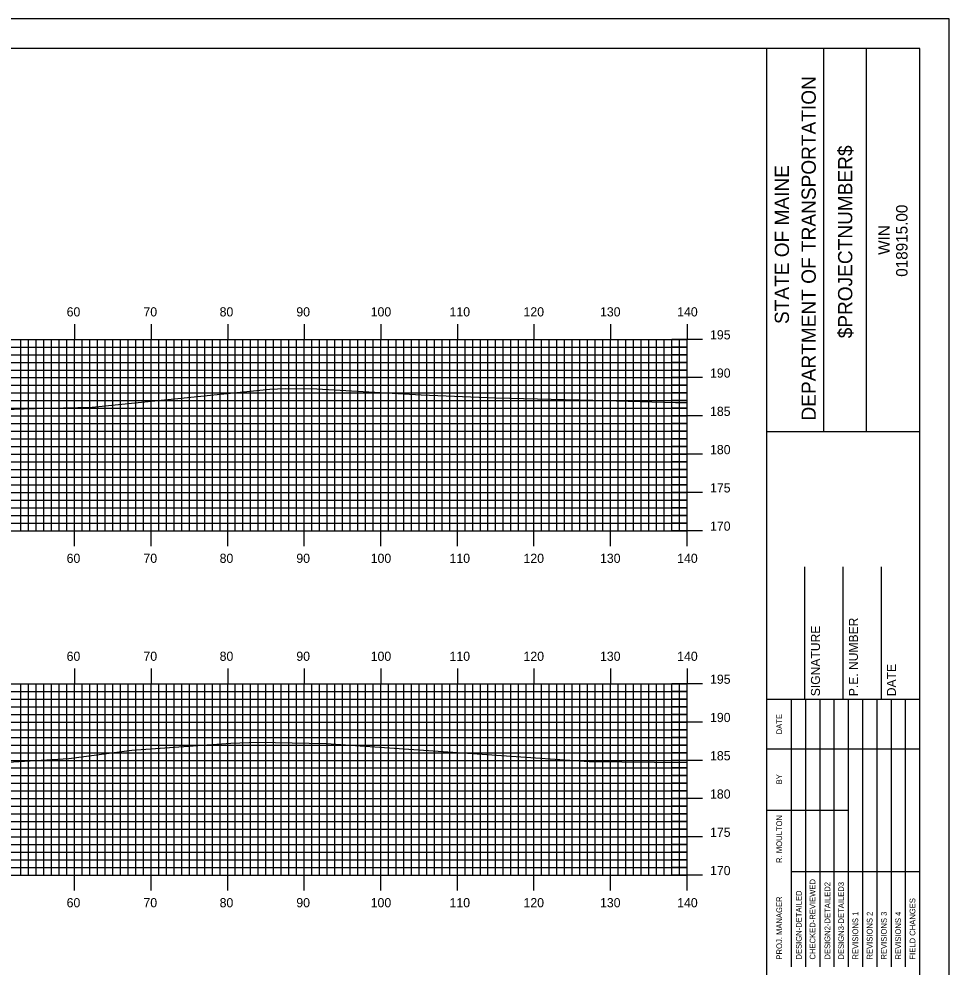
# Model space of a CAD drawing. Extents: x 1823571 to 1823914, y 442310 to 442530.
# Drawn here: x 1823789.6 to 1823911.1, y 442406.1 to 442530 of the extents above; entities that cross this region are included whole.
import ezdxf

# ---------------------------------------------------------------- set-up
doc = ezdxf.new("R2010")
doc.units = 0
for name, color, linetype in [('BORDER', 7, 'Continuous'), ('H_V ANNOTATION', 7, 'Continuous'), ('MAJOR', 7, 'Continuous'), ('MINOR', 7, 'Continuous'), ('PLOT BOUNDARY', 7, 'Continuous'), ('S_Roadway_Centerline', 7, 'Continuous')]:
    doc.layers.add(name, color=color, linetype=linetype)

msp = doc.modelspace()

# ---------------------------------------------------------------- linework, layer by layer
at = {"layer": 'BORDER'}
for p, q in [((1823887.3, 442316.11), (1823887.3, 442526.11)), ((1823894.76, 442476.1), (1823894.76, 442526.1)), ((1823900.35, 442476.1), (1823900.35, 442526.1)), ((1823887.3, 442476.09), (1823907.3, 442476.09)), ((1823892.3, 442441.11), (1823892.3, 442458.41)), ((1823897.3, 442441.11), (1823897.3, 442458.41)), ((1823902.3, 442441.11), (1823902.3, 442458.41)), ((1823887.3, 442441.11), (1823907.3, 442441.11))]:
    msp.add_line(p, q, dxfattribs=at)
msp.add_lwpolyline([(1823587.3, 442316.11), (1823907.3, 442316.11), (1823907.3, 442526.11), (1823587.3, 442526.11)], close=True, dxfattribs=at)
for points in [[(1823890.53, 442434.61), (1823890.53, 442441.11)], [(1823892.4, 442406.12), (1823892.4, 442441.11)], [(1823894.26, 442441.11), (1823894.26, 442406.12)], [(1823896.12, 442406.12), (1823896.12, 442441.11)], [(1823897.99, 442406.12), (1823897.99, 442441.11)], [(1823899.85, 442406.12), (1823899.85, 442441.11)], [(1823901.71, 442406.12), (1823901.71, 442441.11)], [(1823903.58, 442406.12), (1823903.58, 442441.11)], [(1823905.44, 442406.12), (1823905.44, 442441.11)], [(1823890.53, 442406.12), (1823890.53, 442439.7)], [(1823887.3, 442434.61), (1823907.3, 442434.61)], [(1823887.3, 442426.61), (1823890.53, 442426.61)], [(1823890.53, 442426.61), (1823897.98, 442426.61)], [(1823890.53, 442418.61), (1823907.3, 442418.61)]]:
    msp.add_lwpolyline(points, dxfattribs=at)
at = {"layer": 'MAJOR'}
for p, q in [((1823796.9, 442490.12), (1823796.9, 442488.12)), ((1823806.9, 442490.12), (1823806.9, 442488.12)), ((1823816.9, 442490.12), (1823816.9, 442488.12)), ((1823826.9, 442490.12), (1823826.9, 442488.12)), ((1823836.9, 442490.12), (1823836.9, 442488.12)), ((1823846.9, 442490.12), (1823846.9, 442488.12)), ((1823856.9, 442490.12), (1823856.9, 442488.12)), ((1823866.9, 442490.12), (1823866.9, 442488.12)), ((1823876.9, 442490.12), (1823876.9, 442488.12)), ((1823596.9, 442488.12), (1823876.9, 442488.12)), ((1823596.9, 442488.12), (1823876.9, 442488.12)), ((1823796.9, 442463.12), (1823796.9, 442488.12)), ((1823806.9, 442463.12), (1823806.9, 442488.12)), ((1823816.9, 442463.12), (1823816.9, 442488.12)), ((1823826.9, 442463.12), (1823826.9, 442488.12)), ((1823836.9, 442463.12), (1823836.9, 442488.12)), ((1823846.9, 442463.12), (1823846.9, 442488.12)), ((1823856.9, 442463.12), (1823856.9, 442488.12)), ((1823866.9, 442463.12), (1823866.9, 442488.12)), ((1823878.9, 442488.12), (1823874.9, 442488.12)), ((1823876.9, 442463.12), (1823876.9, 442488.12)), ((1823876.9, 442463.12), (1823876.9, 442488.12)), ((1823596.9, 442483.12), (1823876.9, 442483.12)), ((1823878.9, 442483.12), (1823874.9, 442483.12)), ((1823596.9, 442478.12), (1823876.9, 442478.12)), ((1823878.9, 442478.12), (1823874.9, 442478.12)), ((1823596.9, 442473.12), (1823876.9, 442473.12)), ((1823878.9, 442473.12), (1823874.9, 442473.12)), ((1823596.9, 442468.12), (1823876.9, 442468.12)), ((1823878.9, 442468.12), (1823874.9, 442468.12)), ((1823596.9, 442463.12), (1823876.9, 442463.12)), ((1823596.9, 442463.12), (1823876.9, 442463.12)), ((1823796.9, 442461.11), (1823796.9, 442463.12)), ((1823806.9, 442461.11), (1823806.9, 442463.12)), ((1823816.9, 442461.11), (1823816.9, 442463.12)), ((1823826.9, 442461.11), (1823826.9, 442463.12)), ((1823836.9, 442461.11), (1823836.9, 442463.12)), ((1823846.9, 442461.11), (1823846.9, 442463.12)), ((1823856.9, 442461.11), (1823856.9, 442463.12)), ((1823866.9, 442461.11), (1823866.9, 442463.12)), ((1823878.9, 442463.12), (1823874.9, 442463.12)), ((1823876.9, 442461.11), (1823876.9, 442463.12)), ((1823796.9, 442445.12), (1823796.9, 442443.12)), ((1823806.9, 442445.12), (1823806.9, 442443.12)), ((1823816.9, 442445.12), (1823816.9, 442443.12)), ((1823826.9, 442445.12), (1823826.9, 442443.12)), ((1823836.9, 442445.12), (1823836.9, 442443.12)), ((1823846.9, 442445.12), (1823846.9, 442443.12)), ((1823856.9, 442445.12), (1823856.9, 442443.12)), ((1823866.9, 442445.12), (1823866.9, 442443.12)), ((1823876.9, 442445.12), (1823876.9, 442443.12)), ((1823596.9, 442443.12), (1823876.9, 442443.12)), ((1823596.9, 442443.12), (1823876.9, 442443.12)), ((1823796.9, 442418.12), (1823796.9, 442443.12)), ((1823806.9, 442418.12), (1823806.9, 442443.12)), ((1823816.9, 442418.12), (1823816.9, 442443.12)), ((1823826.9, 442418.12), (1823826.9, 442443.12)), ((1823836.9, 442418.12), (1823836.9, 442443.12)), ((1823846.9, 442418.12), (1823846.9, 442443.12)), ((1823856.9, 442418.12), (1823856.9, 442443.12)), ((1823866.9, 442418.12), (1823866.9, 442443.12)), ((1823878.9, 442443.12), (1823874.9, 442443.12)), ((1823876.9, 442418.12), (1823876.9, 442443.12)), ((1823876.9, 442418.12), (1823876.9, 442443.12)), ((1823596.9, 442438.12), (1823876.9, 442438.12)), ((1823878.9, 442438.12), (1823874.9, 442438.12)), ((1823596.9, 442433.12), (1823876.9, 442433.12)), ((1823878.9, 442433.12), (1823874.9, 442433.12)), ((1823596.9, 442428.12), (1823876.9, 442428.12)), ((1823878.9, 442428.12), (1823874.9, 442428.12)), ((1823596.9, 442423.12), (1823876.9, 442423.12)), ((1823878.9, 442423.12), (1823874.9, 442423.12)), ((1823596.9, 442418.12), (1823876.9, 442418.12)), ((1823596.9, 442418.12), (1823876.9, 442418.12)), ((1823796.9, 442416.11), (1823796.9, 442418.12)), ((1823806.9, 442416.11), (1823806.9, 442418.12)), ((1823816.9, 442416.11), (1823816.9, 442418.12)), ((1823826.9, 442416.11), (1823826.9, 442418.12)), ((1823836.9, 442416.11), (1823836.9, 442418.12)), ((1823846.9, 442416.11), (1823846.9, 442418.12)), ((1823856.9, 442416.11), (1823856.9, 442418.12)), ((1823866.9, 442416.11), (1823866.9, 442418.12)), ((1823878.9, 442418.12), (1823874.9, 442418.12)), ((1823876.9, 442416.11), (1823876.9, 442418.12))]:
    msp.add_line(p, q, dxfattribs=at)
at = {"layer": 'MINOR'}
for p, q in [((1823789.9, 442463.12), (1823789.9, 442488.12)), ((1823790.9, 442463.12), (1823790.9, 442488.12)), ((1823791.9, 442463.12), (1823791.9, 442488.12)), ((1823792.9, 442463.12), (1823792.9, 442488.12)), ((1823793.9, 442463.12), (1823793.9, 442488.12)), ((1823794.9, 442463.12), (1823794.9, 442488.12)), ((1823795.9, 442463.12), (1823795.9, 442488.12)), ((1823797.9, 442463.12), (1823797.9, 442488.12)), ((1823798.9, 442463.12), (1823798.9, 442488.12)), ((1823799.9, 442463.12), (1823799.9, 442488.12)), ((1823800.9, 442463.12), (1823800.9, 442488.12)), ((1823801.9, 442463.12), (1823801.9, 442488.12)), ((1823802.9, 442463.12), (1823802.9, 442488.12)), ((1823803.9, 442463.12), (1823803.9, 442488.12)), ((1823804.9, 442463.12), (1823804.9, 442488.12)), ((1823805.9, 442463.12), (1823805.9, 442488.12)), ((1823807.9, 442463.12), (1823807.9, 442488.12)), ((1823808.9, 442463.12), (1823808.9, 442488.12)), ((1823809.9, 442463.12), (1823809.9, 442488.12)), ((1823810.9, 442463.12), (1823810.9, 442488.12)), ((1823811.9, 442463.12), (1823811.9, 442488.12)), ((1823812.9, 442463.12), (1823812.9, 442488.12)), ((1823813.9, 442463.12), (1823813.9, 442488.12)), ((1823814.9, 442463.12), (1823814.9, 442488.12)), ((1823815.9, 442463.12), (1823815.9, 442488.12)), ((1823817.9, 442463.12), (1823817.9, 442488.12)), ((1823818.9, 442463.12), (1823818.9, 442488.12)), ((1823819.9, 442463.12), (1823819.9, 442488.12)), ((1823820.9, 442463.12), (1823820.9, 442488.12)), ((1823821.9, 442463.12), (1823821.9, 442488.12)), ((1823822.9, 442463.12), (1823822.9, 442488.12)), ((1823823.9, 442463.12), (1823823.9, 442488.12)), ((1823824.9, 442463.12), (1823824.9, 442488.12)), ((1823825.9, 442463.12), (1823825.9, 442488.12)), ((1823827.9, 442463.12), (1823827.9, 442488.12)), ((1823828.9, 442463.12), (1823828.9, 442488.12)), ((1823829.9, 442463.12), (1823829.9, 442488.12)), ((1823830.9, 442463.12), (1823830.9, 442488.12)), ((1823831.9, 442463.12), (1823831.9, 442488.12)), ((1823832.9, 442463.12), (1823832.9, 442488.12)), ((1823833.9, 442463.12), (1823833.9, 442488.12)), ((1823834.9, 442463.12), (1823834.9, 442488.12)), ((1823835.9, 442463.12), (1823835.9, 442488.12)), ((1823837.9, 442463.12), (1823837.9, 442488.12)), ((1823838.9, 442463.12), (1823838.9, 442488.12)), ((1823839.9, 442463.12), (1823839.9, 442488.12)), ((1823840.9, 442463.12), (1823840.9, 442488.12)), ((1823841.9, 442463.12), (1823841.9, 442488.12)), ((1823842.9, 442463.12), (1823842.9, 442488.12)), ((1823843.9, 442463.12), (1823843.9, 442488.12)), ((1823844.9, 442463.12), (1823844.9, 442488.12)), ((1823845.9, 442463.12), (1823845.9, 442488.12)), ((1823847.9, 442463.12), (1823847.9, 442488.12)), ((1823848.9, 442463.12), (1823848.9, 442488.12)), ((1823849.9, 442463.12), (1823849.9, 442488.12)), ((1823850.9, 442463.12), (1823850.9, 442488.12)), ((1823851.9, 442463.12), (1823851.9, 442488.12)), ((1823852.9, 442463.12), (1823852.9, 442488.12)), ((1823853.9, 442463.12), (1823853.9, 442488.12)), ((1823854.9, 442463.12), (1823854.9, 442488.12)), ((1823855.9, 442463.12), (1823855.9, 442488.12)), ((1823857.9, 442463.12), (1823857.9, 442488.12)), ((1823858.9, 442463.12), (1823858.9, 442488.12)), ((1823859.9, 442463.12), (1823859.9, 442488.12)), ((1823860.9, 442463.12), (1823860.9, 442488.12)), ((1823861.9, 442463.12), (1823861.9, 442488.12)), ((1823862.9, 442463.12), (1823862.9, 442488.12)), ((1823863.9, 442463.12), (1823863.9, 442488.12)), ((1823864.9, 442463.12), (1823864.9, 442488.12)), ((1823865.9, 442463.12), (1823865.9, 442488.12)), ((1823867.9, 442463.12), (1823867.9, 442488.12)), ((1823868.9, 442463.12), (1823868.9, 442488.12)), ((1823869.9, 442463.12), (1823869.9, 442488.12)), ((1823870.9, 442463.12), (1823870.9, 442488.12)), ((1823871.9, 442463.12), (1823871.9, 442488.12)), ((1823872.9, 442463.12), (1823872.9, 442488.12)), ((1823873.9, 442463.12), (1823873.9, 442488.12)), ((1823874.9, 442463.12), (1823874.9, 442488.12)), ((1823875.9, 442463.12), (1823875.9, 442488.12)), ((1823596.9, 442487.12), (1823876.9, 442487.12)), ((1823596.9, 442486.12), (1823876.9, 442486.12)), ((1823876.9, 442487.12), (1823874.9, 442487.12)), ((1823876.9, 442486.12), (1823874.9, 442486.12)), ((1823596.9, 442485.12), (1823876.9, 442485.12)), ((1823876.9, 442485.12), (1823874.9, 442485.12)), ((1823596.9, 442484.12), (1823876.9, 442484.12)), ((1823876.9, 442484.12), (1823874.9, 442484.12)), ((1823596.9, 442482.12), (1823876.9, 442482.12)), ((1823596.9, 442481.12), (1823876.9, 442481.12)), ((1823876.9, 442482.12), (1823874.9, 442482.12)), ((1823876.9, 442481.12), (1823874.9, 442481.12)), ((1823596.9, 442480.12), (1823876.9, 442480.12)), ((1823876.9, 442480.12), (1823874.9, 442480.12)), ((1823596.9, 442479.12), (1823876.9, 442479.12)), ((1823876.9, 442479.12), (1823874.9, 442479.12)), ((1823596.9, 442477.12), (1823876.9, 442477.12)), ((1823876.9, 442477.12), (1823874.9, 442477.12)), ((1823596.9, 442476.12), (1823876.9, 442476.12)), ((1823596.9, 442475.12), (1823876.9, 442475.12)), ((1823876.9, 442476.12), (1823874.9, 442476.12)), ((1823876.9, 442475.12), (1823874.9, 442475.12)), ((1823596.9, 442474.12), (1823876.9, 442474.12)), ((1823876.9, 442474.12), (1823874.9, 442474.12)), ((1823596.9, 442472.12), (1823876.9, 442472.12)), ((1823876.9, 442472.12), (1823874.9, 442472.12)), ((1823596.9, 442471.12), (1823876.9, 442471.12)), ((1823596.9, 442470.12), (1823876.9, 442470.12)), ((1823876.9, 442471.12), (1823874.9, 442471.12)), ((1823876.9, 442470.12), (1823874.9, 442470.12)), ((1823596.9, 442469.12), (1823876.9, 442469.12)), ((1823876.9, 442469.12), (1823874.9, 442469.12)), ((1823596.9, 442467.12), (1823876.9, 442467.12)), ((1823876.9, 442467.12), (1823874.9, 442467.12)), ((1823596.9, 442466.12), (1823876.9, 442466.12)), ((1823596.9, 442465.12), (1823876.9, 442465.12)), ((1823876.9, 442466.12), (1823874.9, 442466.12)), ((1823876.9, 442465.12), (1823874.9, 442465.12)), ((1823596.9, 442464.12), (1823876.9, 442464.12)), ((1823876.9, 442464.12), (1823874.9, 442464.12)), ((1823789.9, 442418.12), (1823789.9, 442443.12)), ((1823790.9, 442418.12), (1823790.9, 442443.12)), ((1823791.9, 442418.12), (1823791.9, 442443.12)), ((1823792.9, 442418.12), (1823792.9, 442443.12)), ((1823793.9, 442418.12), (1823793.9, 442443.12)), ((1823794.9, 442418.12), (1823794.9, 442443.12)), ((1823795.9, 442418.12), (1823795.9, 442443.12)), ((1823797.9, 442418.12), (1823797.9, 442443.12)), ((1823798.9, 442418.12), (1823798.9, 442443.12)), ((1823799.9, 442418.12), (1823799.9, 442443.12)), ((1823800.9, 442418.12), (1823800.9, 442443.12)), ((1823801.9, 442418.12), (1823801.9, 442443.12)), ((1823802.9, 442418.12), (1823802.9, 442443.12)), ((1823803.9, 442418.12), (1823803.9, 442443.12)), ((1823804.9, 442418.12), (1823804.9, 442443.12)), ((1823805.9, 442418.12), (1823805.9, 442443.12)), ((1823807.9, 442418.12), (1823807.9, 442443.12)), ((1823808.9, 442418.12), (1823808.9, 442443.12)), ((1823809.9, 442418.12), (1823809.9, 442443.12)), ((1823810.9, 442418.12), (1823810.9, 442443.12)), ((1823811.9, 442418.12), (1823811.9, 442443.12)), ((1823812.9, 442418.12), (1823812.9, 442443.12)), ((1823813.9, 442418.12), (1823813.9, 442443.12)), ((1823814.9, 442418.12), (1823814.9, 442443.12)), ((1823815.9, 442418.12), (1823815.9, 442443.12)), ((1823817.9, 442418.12), (1823817.9, 442443.12)), ((1823818.9, 442418.12), (1823818.9, 442443.12)), ((1823819.9, 442418.12), (1823819.9, 442443.12)), ((1823820.9, 442418.12), (1823820.9, 442443.12)), ((1823821.9, 442418.12), (1823821.9, 442443.12)), ((1823822.9, 442418.12), (1823822.9, 442443.12)), ((1823823.9, 442418.12), (1823823.9, 442443.12)), ((1823824.9, 442418.12), (1823824.9, 442443.12)), ((1823825.9, 442418.12), (1823825.9, 442443.12)), ((1823827.9, 442418.12), (1823827.9, 442443.12)), ((1823828.9, 442418.12), (1823828.9, 442443.12)), ((1823829.9, 442418.12), (1823829.9, 442443.12)), ((1823830.9, 442418.12), (1823830.9, 442443.12)), ((1823831.9, 442418.12), (1823831.9, 442443.12)), ((1823832.9, 442418.12), (1823832.9, 442443.12)), ((1823833.9, 442418.12), (1823833.9, 442443.12)), ((1823834.9, 442418.12), (1823834.9, 442443.12)), ((1823835.9, 442418.12), (1823835.9, 442443.12)), ((1823837.9, 442418.12), (1823837.9, 442443.12)), ((1823838.9, 442418.12), (1823838.9, 442443.12)), ((1823839.9, 442418.12), (1823839.9, 442443.12)), ((1823840.9, 442418.12), (1823840.9, 442443.12)), ((1823841.9, 442418.12), (1823841.9, 442443.12)), ((1823842.9, 442418.12), (1823842.9, 442443.12)), ((1823843.9, 442418.12), (1823843.9, 442443.12)), ((1823844.9, 442418.12), (1823844.9, 442443.12)), ((1823845.9, 442418.12), (1823845.9, 442443.12)), ((1823847.9, 442418.12), (1823847.9, 442443.12)), ((1823848.9, 442418.12), (1823848.9, 442443.12)), ((1823849.9, 442418.12), (1823849.9, 442443.12)), ((1823850.9, 442418.12), (1823850.9, 442443.12)), ((1823851.9, 442418.12), (1823851.9, 442443.12)), ((1823852.9, 442418.12), (1823852.9, 442443.12)), ((1823853.9, 442418.12), (1823853.9, 442443.12)), ((1823854.9, 442418.12), (1823854.9, 442443.12)), ((1823855.9, 442418.12), (1823855.9, 442443.12)), ((1823857.9, 442418.12), (1823857.9, 442443.12)), ((1823858.9, 442418.12), (1823858.9, 442443.12)), ((1823859.9, 442418.12), (1823859.9, 442443.12)), ((1823860.9, 442418.12), (1823860.9, 442443.12)), ((1823861.9, 442418.12), (1823861.9, 442443.12)), ((1823862.9, 442418.12), (1823862.9, 442443.12)), ((1823863.9, 442418.12), (1823863.9, 442443.12)), ((1823864.9, 442418.12), (1823864.9, 442443.12)), ((1823865.9, 442418.12), (1823865.9, 442443.12)), ((1823867.9, 442418.12), (1823867.9, 442443.12)), ((1823868.9, 442418.12), (1823868.9, 442443.12)), ((1823869.9, 442418.12), (1823869.9, 442443.12)), ((1823870.9, 442418.12), (1823870.9, 442443.12)), ((1823871.9, 442418.12), (1823871.9, 442443.12)), ((1823872.9, 442418.12), (1823872.9, 442443.12)), ((1823873.9, 442418.12), (1823873.9, 442443.12)), ((1823874.9, 442418.12), (1823874.9, 442443.12)), ((1823875.9, 442418.12), (1823875.9, 442443.12)), ((1823596.9, 442442.12), (1823876.9, 442442.12)), ((1823876.9, 442442.12), (1823874.9, 442442.12)), ((1823596.9, 442441.12), (1823876.9, 442441.12)), ((1823876.9, 442441.12), (1823874.9, 442441.12)), ((1823596.9, 442440.12), (1823876.9, 442440.12)), ((1823596.9, 442439.12), (1823876.9, 442439.12)), ((1823876.9, 442440.12), (1823874.9, 442440.12)), ((1823876.9, 442439.12), (1823874.9, 442439.12)), ((1823596.9, 442437.12), (1823876.9, 442437.12)), ((1823876.9, 442437.12), (1823874.9, 442437.12)), ((1823596.9, 442436.12), (1823876.9, 442436.12)), ((1823876.9, 442436.12), (1823874.9, 442436.12)), ((1823596.9, 442435.12), (1823876.9, 442435.12)), ((1823596.9, 442434.12), (1823876.9, 442434.12)), ((1823876.9, 442435.12), (1823874.9, 442435.12)), ((1823876.9, 442434.12), (1823874.9, 442434.12)), ((1823596.9, 442432.12), (1823876.9, 442432.12)), ((1823876.9, 442432.12), (1823874.9, 442432.12)), ((1823596.9, 442431.12), (1823876.9, 442431.12)), ((1823876.9, 442431.12), (1823874.9, 442431.12)), ((1823596.9, 442430.12), (1823876.9, 442430.12)), ((1823596.9, 442429.12), (1823876.9, 442429.12)), ((1823876.9, 442430.12), (1823874.9, 442430.12)), ((1823876.9, 442429.12), (1823874.9, 442429.12)), ((1823596.9, 442427.12), (1823876.9, 442427.12)), ((1823876.9, 442427.12), (1823874.9, 442427.12)), ((1823596.9, 442426.12), (1823876.9, 442426.12)), ((1823876.9, 442426.12), (1823874.9, 442426.12)), ((1823596.9, 442425.12), (1823876.9, 442425.12)), ((1823876.9, 442425.12), (1823874.9, 442425.12)), ((1823596.9, 442424.12), (1823876.9, 442424.12)), ((1823876.9, 442424.12), (1823874.9, 442424.12)), ((1823596.9, 442422.12), (1823876.9, 442422.12)), ((1823876.9, 442422.12), (1823874.9, 442422.12)), ((1823596.9, 442421.12), (1823876.9, 442421.12)), ((1823876.9, 442421.12), (1823874.9, 442421.12)), ((1823596.9, 442420.12), (1823876.9, 442420.12)), ((1823876.9, 442420.12), (1823874.9, 442420.12)), ((1823596.9, 442419.12), (1823876.9, 442419.12)), ((1823876.9, 442419.12), (1823874.9, 442419.12))]:
    msp.add_line(p, q, dxfattribs=at)
at = {"layer": 'PLOT BOUNDARY'}
msp.add_lwpolyline([(1823571.11, 442309.99), (1823911.11, 442309.99), (1823911.11, 442529.99), (1823571.11, 442529.99)], close=True, dxfattribs=at)
at = {"layer": 'S_Roadway_Centerline'}
for points in [[(1823784.96, 442478.89), (1823791.65, 442479.08), (1823799.21, 442479.26), (1823822.39, 442481.62), (1823824.39, 442481.7), (1823828.53, 442481.64), (1823842.17, 442480.87), (1823851.94, 442480.5), (1823864.6, 442480.19), (1823875.38, 442479.89), (1823876.9, 442479.87)], [(1823787.48, 442432.84), (1823796.16, 442433.36), (1823804.37, 442434.45), (1823817.32, 442435.36), (1823820.9, 442435.5), (1823829.78, 442435.31), (1823864.11, 442432.97), (1823876.9, 442432.86)]]:
    msp.add_lwpolyline(points, dxfattribs=at)

# ---------------------------------------------------------------- texts
at = {"layer": 'BORDER'}
for s, height, p in [('DEPARTMENT OF TRANSPORTATION', 1.8635, (1823893.71, 442477.52)), ('$PROJECTNUMBER$', 1.8635, (1823898.48, 442488.26)), ('STATE OF MAINE', 1.8635, (1823890.21, 442490.13)), ('018915.00', 1.491, (1823905.69, 442496.3)), ('WIN', 1.491, (1823903.37, 442499.17)), ('P.E. NUMBER', 1.1811, (1823899.22, 442441.5)), ('SIGNATURE', 1.181, (1823894.26, 442441.5)), ('DATE', 1.181, (1823904.18, 442441.5)), ('DATE', 0.743, (1823889.31, 442436.52)), ('BY', 0.743, (1823889.31, 442429.98)), ('R. MOULTON', 0.745, (1823889.31, 442419.72)), ('CHECKED-REVIEWED', 0.7455, (1823893.66, 442407.09)), ('DESIGN2-DETAILED2', 0.7455, (1823895.6, 442407.09)), ('DESIGN3-DETAILED3', 0.7455, (1823897.39, 442407.09)), ('DESIGN-DETAILED', 0.7455, (1823891.87, 442407.09)), ('PROJ. MANAGER', 0.7455, (1823889.31, 442407.09)), ('FIELD CHANGES', 0.7455, (1823906.71, 442407.09)), ('REVISIONS 1', 0.7455, (1823899.25, 442407.09)), ('REVISIONS 2', 0.7455, (1823901.12, 442407.09)), ('REVISIONS 3', 0.7455, (1823902.98, 442407.09)), ('REVISIONS 4', 0.7455, (1823904.84, 442407.09))]:
    msp.add_text(s, height=height, rotation=90, dxfattribs=at).set_placement(p)
at = {"layer": 'H_V ANNOTATION'}
for s, p in [('60', (1823795.87, 442491.12)), ('70', (1823805.9, 442491.12)), ('80', (1823815.85, 442491.12)), ('90', (1823825.87, 442491.12)), ('100', (1823835.58, 442491.12)), ('110', (1823845.88, 442491.12)), ('120', (1823855.54, 442491.12)), ('130', (1823865.53, 442491.12)), ('140', (1823875.61, 442491.12)), ('195', (1823879.9, 442488.12)), ('190', (1823879.9, 442483.12)), ('185', (1823879.9, 442478.12)), ('180', (1823879.9, 442473.12)), ('175', (1823879.9, 442468.12)), ('170', (1823879.9, 442463.12)), ('60', (1823795.87, 442458.92)), ('70', (1823805.9, 442458.92)), ('80', (1823815.85, 442458.92)), ('90', (1823825.87, 442458.92)), ('100', (1823835.58, 442458.92)), ('110', (1823845.88, 442458.92)), ('120', (1823855.54, 442458.92)), ('130', (1823865.53, 442458.92)), ('140', (1823875.61, 442458.92)), ('60', (1823795.87, 442446.12)), ('70', (1823805.9, 442446.12)), ('80', (1823815.85, 442446.12)), ('90', (1823825.87, 442446.12)), ('100', (1823835.58, 442446.12)), ('110', (1823845.88, 442446.12)), ('120', (1823855.54, 442446.12)), ('130', (1823865.53, 442446.12)), ('140', (1823875.61, 442446.12)), ('195', (1823879.9, 442443.12)), ('190', (1823879.9, 442438.12)), ('185', (1823879.9, 442433.12)), ('180', (1823879.9, 442428.12)), ('175', (1823879.9, 442423.12)), ('170', (1823879.9, 442418.12)), ('60', (1823795.87, 442413.92)), ('70', (1823805.9, 442413.92)), ('80', (1823815.85, 442413.92)), ('90', (1823825.87, 442413.92)), ('100', (1823835.58, 442413.92)), ('110', (1823845.88, 442413.92)), ('120', (1823855.54, 442413.92)), ('130', (1823865.53, 442413.92)), ('140', (1823875.61, 442413.92))]:
    msp.add_text(s, height=1.2, dxfattribs=at).set_placement(p)

doc.saveas('drawing.dxf')
